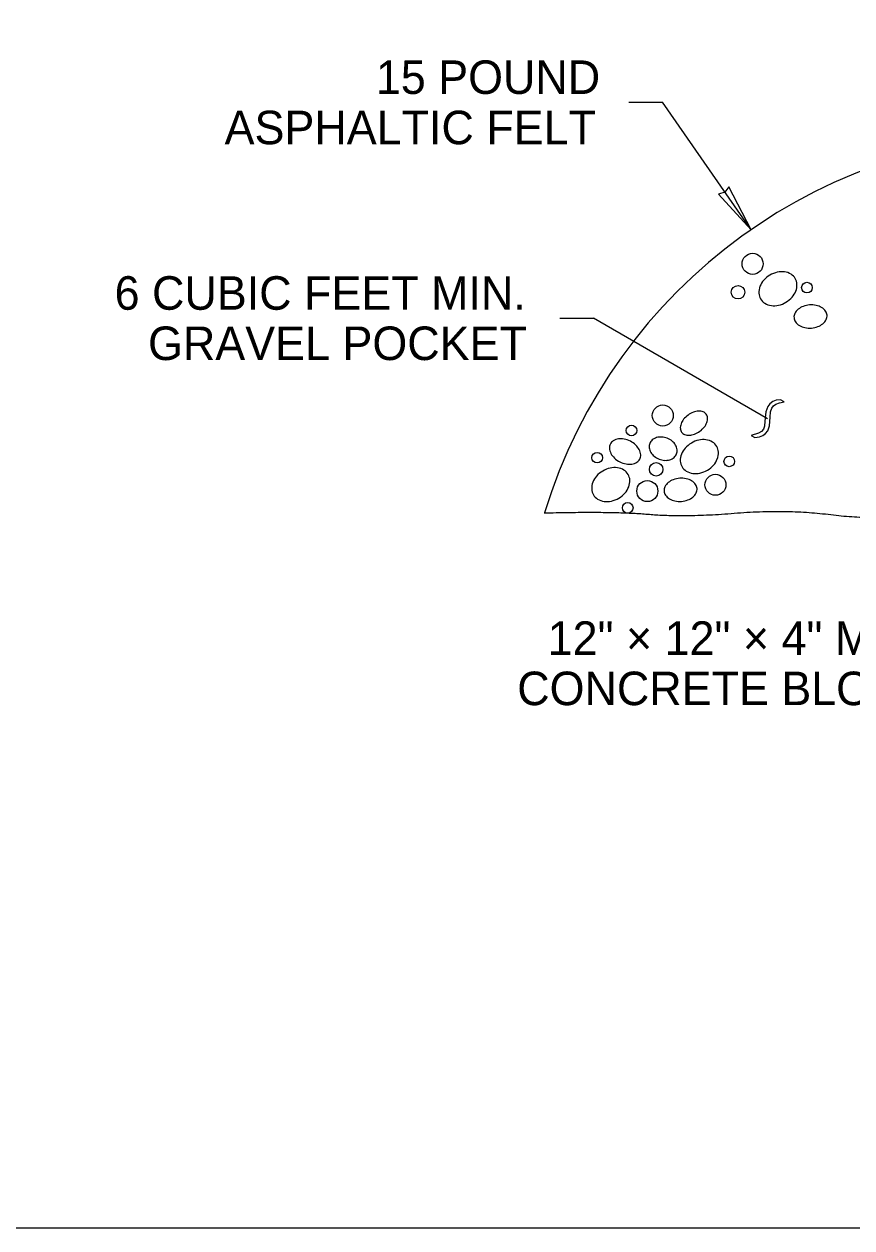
# Model space of a CAD drawing. Extents: x 99862 to 103151, y 100000 to 102076.
# Drawn here: x 101292 to 101687, y 100000 to 100574 of the extents above; entities that cross this region are included whole.
import ezdxf

# ---------------------------------------------------------------- set-up
doc = ezdxf.new("R2010")
doc.units = 0
for name, color, linetype in [('Level 1', 7, 'Continuous'), ('Level 10', 7, 'Continuous'), ('Level 15', 7, 'Continuous'), ('Level 20', 7, 'Continuous')]:
    doc.layers.add(name, color=color, linetype=linetype)

msp = doc.modelspace()

# ---------------------------------------------------------------- linework, layer by layer
at = {"layer": 'Level 1'}
msp.add_lwpolyline([(99862, 99999.5), (103151, 99999.5), (103151, 102075.5), (99862, 102075.5)], close=True, dxfattribs=at)
msp.add_arc((101784.76, 100265.79), 255.78, 89.02946, 162.96913, dxfattribs=at)
msp.add_open_spline([(101540.14, 100340.7), (101572.89, 100341.52), (101607.18, 100338.57), (101654.79, 100342.57), (101698.15, 100337.27), (101736.73, 100341.25), (101771.26, 100339.65)], degree=2, dxfattribs=at)
at = {"layer": 'Level 10'}
for centre, radius in [((101639.54, 100459.54), 5.02), ((101632.56, 100445.99), 3.22), ((101665.45, 100448.18), 2.54), ((101596.68, 100387.18), 5.02), ((101581.73, 100380.01), 2.54), ((101565.39, 100367.05), 2.54), ((101593.5, 100361.47), 3.22), ((101628.38, 100365.26), 2.54), ((101621.8, 100354.1), 5.02), ((101589.31, 100351.11), 5.02), ((101579.94, 100343.13), 2.54)]:
    msp.add_circle(centre, radius, dxfattribs=at)
for centre, radius, start, end in [((101653.97, 100443.66), 12.2, 102.54735, 120.55568), ((101653.45, 100446.01), 9.8, 82.43038, 102.54735), ((101653.69, 100447.84), 7.95, 58.38014, 82.43038), ((101654.73, 100449.53), 5.97, 30.55568, 58.38014), ((101650.45, 100445.93), 7.95, 158.68099, 182.73122), ((101652.17, 100445.25), 9.8, 138.56401, 158.68099), ((101653.97, 100443.66), 12.2, 120.55568, 138.56401), ((101654.73, 100449.53), 5.97, 2.73122, 30.55568), ((101652.75, 100449.43), 7.95, 338.68099, 2.73122), ((101648.47, 100445.83), 5.97, 182.73122, 210.55568), ((101649.23, 100451.7), 12.2, 300.55568, 318.56401), ((101651.03, 100450.1), 9.8, 318.56401, 338.68099), ((101648.47, 100445.83), 5.97, 210.55568, 238.38014), ((101649.51, 100447.52), 7.95, 238.38014, 262.43038), ((101649.75, 100449.35), 9.8, 262.43038, 282.54735), ((101649.23, 100451.7), 12.2, 282.54735, 300.55568), ((101665.17, 100433.14), 6.14, 129.27062, 153.66865), ((101666.55, 100431.45), 8.32, 110.47593, 129.27062), ((101667.58, 100428.69), 11.27, 94.34319, 110.47593), ((101667.58, 100428.69), 11.27, 78.21045, 94.34319), ((101668.19, 100431.57), 8.32, 59.41576, 78.21045), ((101669.3, 100433.45), 6.14, 35.01773, 59.41576), ((101663.18, 100434.12), 3.92, 153.66865, 184.34319), ((101663.18, 100434.12), 3.92, 184.34319, 215.01773), ((101665, 100435.4), 6.14, 215.01773, 239.41576), ((101669.13, 100435.71), 6.14, 309.27062, 333.66865), ((101671.12, 100434.73), 3.92, 4.34319, 35.01773), ((101671.12, 100434.73), 3.92, 333.66865, 4.34319), ((101666.11, 100437.28), 8.32, 239.41576, 258.21045), ((101666.71, 100440.16), 11.27, 258.21045, 274.34319), ((101666.71, 100440.16), 11.27, 274.34319, 290.47593), ((101667.74, 100437.4), 8.32, 290.47593, 309.27062), ((101615.21, 100378.46), 11.02, 126.08477, 141.32523), ((101615.21, 100378.46), 11.02, 110.84431, 126.08477), ((101614.08, 100381.43), 7.84, 92.74951, 110.84431), ((101613.96, 100383.75), 5.51, 68.28483, 92.74951), ((101614.81, 100385.89), 3.22, 36.08477, 68.28483), ((101614.81, 100385.89), 3.22, 3.88471, 36.08477), ((101612.52, 100385.73), 5.51, 339.42002, 3.88471), ((101610.55, 100381.26), 5.51, 159.42002, 183.88471), ((101608.26, 100381.11), 3.22, 183.88471, 216.08477), ((101612.72, 100380.45), 7.84, 141.32523, 159.42002), ((101607.86, 100388.54), 11.02, 306.08477, 321.32523), ((101610.35, 100386.55), 7.84, 321.32523, 339.42002), ((101575.15, 100371.79), 3.92, 122.21424, 152.88878), ((101576.33, 100369.91), 6.14, 97.81622, 122.21424), ((101576.63, 100367.74), 8.32, 79.02153, 97.81622), ((101576.07, 100364.85), 11.27, 62.88878, 79.02153), ((101576.07, 100364.85), 11.27, 46.75604, 62.88878), ((101594.42, 100372.3), 4.21, 130.69622, 158.66336), ((101595.36, 100371.21), 5.65, 106.62121, 130.69623), ((101595.75, 100369.92), 6.99, 86.57049, 106.62121), ((101595.64, 100368.16), 8.75, 68.66336, 86.57049), ((101595.64, 100368.16), 8.75, 50.75623, 68.66336), ((101596.75, 100369.52), 6.99, 30.70551, 50.75623), ((101608.26, 100381.11), 3.22, 216.08477, 248.28483), ((101609.11, 100383.24), 5.51, 248.28483, 272.74951), ((101616.5, 100363.53), 12.2, 120.55568, 138.56401), ((101608.99, 100385.56), 7.84, 272.74951, 290.84431), ((101616.5, 100363.53), 12.2, 102.54735, 120.55568), ((101607.86, 100388.54), 11.02, 290.84431, 306.08477), ((101615.97, 100365.88), 9.8, 82.43038, 102.54735), ((101616.22, 100367.71), 7.95, 58.38014, 82.43038), ((101617.26, 100369.4), 5.97, 30.55568, 58.38014), ((101575.15, 100371.79), 3.92, 152.88878, 183.56333), ((101577.36, 100371.93), 6.14, 183.56333, 207.96135), ((101579.29, 100372.95), 8.32, 207.96135, 226.75604), ((101578.08, 100367), 8.32, 27.96135, 46.75604), ((101580.01, 100368.02), 6.14, 3.56333, 27.96135), ((101582.23, 100368.16), 3.92, 332.88878, 3.56333), ((101594.42, 100372.3), 4.21, 158.66336, 186.63049), ((101595.86, 100372.46), 5.65, 186.63049, 210.70551), ((101597.01, 100373.15), 6.99, 210.70551, 230.75623), ((101599.34, 100370.38), 4.21, 310.69623, 338.66336), ((101597.91, 100370.21), 5.65, 6.63049, 30.70551), ((101599.34, 100370.38), 4.21, 338.66336, 6.63049), ((101612.97, 100365.8), 7.95, 158.68099, 182.73122), ((101614.69, 100365.13), 9.8, 138.56401, 158.68099), ((101617.26, 100369.4), 5.97, 2.73122, 30.55568), ((101615.28, 100369.3), 7.95, 338.68099, 2.73122), ((101581.31, 100375.1), 11.27, 226.75604, 242.88878), ((101581.31, 100375.1), 11.27, 242.88878, 259.02152), ((101580.75, 100372.2), 8.32, 259.02152, 277.81622), ((101581.05, 100370.04), 6.14, 277.81622, 302.21424), ((101582.23, 100368.16), 3.92, 302.21424, 332.88878), ((101598.12, 100374.51), 8.75, 230.75623, 248.66336), ((101598.12, 100374.51), 8.75, 248.66336, 266.57049), ((101598.02, 100372.76), 6.99, 266.57049, 286.62121), ((101598.4, 100371.47), 5.65, 286.62121, 310.69623), ((101611, 100365.7), 5.97, 182.73122, 210.55568), ((101611, 100365.7), 5.97, 210.55568, 238.38014), ((101611.76, 100371.57), 12.2, 300.55568, 318.56401), ((101613.56, 100369.98), 9.8, 318.56401, 338.68099), ((101572.44, 100351.77), 9.8, 138.56401, 158.68099), ((101574.24, 100350.18), 12.2, 120.55568, 138.56401), ((101574.24, 100350.18), 12.2, 102.54735, 120.55568), ((101573.72, 100352.53), 9.8, 82.43038, 102.54735), ((101573.96, 100354.36), 7.95, 58.38014, 82.43038), ((101575, 100356.04), 5.97, 30.55568, 58.38014), ((101575, 100356.04), 5.97, 2.73122, 30.55568), ((101605.59, 100345.97), 11.27, 94.34319, 110.47593), ((101605.59, 100345.97), 11.27, 78.21045, 94.34319), ((101612.03, 100367.39), 7.95, 238.38014, 262.43038), ((101606.19, 100348.85), 8.32, 59.41576, 78.21045), ((101612.28, 100369.22), 9.8, 262.43038, 282.54735), ((101611.76, 100371.57), 12.2, 282.54735, 300.55568), ((101570.72, 100352.44), 7.95, 158.68099, 182.73122), ((101568.74, 100352.35), 5.97, 182.73122, 210.55568), ((101571.3, 100356.62), 9.8, 318.56401, 338.68099), ((101573.02, 100355.95), 7.95, 338.68099, 2.73122), ((101601.19, 100351.4), 3.92, 153.66865, 184.34319), ((101601.19, 100351.4), 3.92, 184.34319, 215.01773), ((101603.18, 100350.42), 6.14, 129.27062, 153.66865), ((101604.56, 100348.73), 8.32, 110.47593, 129.27062), ((101607.31, 100350.73), 6.14, 35.01773, 59.41576), ((101609.12, 100352.01), 3.92, 4.34319, 35.01773), ((101609.12, 100352.01), 3.92, 333.66865, 4.34319), ((101568.74, 100352.35), 5.97, 210.55568, 238.38014), ((101569.78, 100354.03), 7.95, 238.38014, 262.43038), ((101570.02, 100355.86), 9.8, 262.43038, 282.54735), ((101569.5, 100358.21), 12.2, 282.54735, 300.55568), ((101569.5, 100358.21), 12.2, 300.55568, 318.56401), ((101603.01, 100352.68), 6.14, 215.01773, 239.41576), ((101604.12, 100354.56), 8.32, 239.41576, 258.21045), ((101604.72, 100357.44), 11.27, 258.21045, 274.34319), ((101604.72, 100357.44), 11.27, 274.34319, 290.47593), ((101605.75, 100354.68), 8.32, 290.47593, 309.27062), ((101607.13, 100352.99), 6.14, 309.27062, 333.66865)]:
    msp.add_arc(centre, radius, start, end, dxfattribs=at)
at = {"layer": 'Level 15'}
for p, q in [((101580.49, 100536.61), (101596.49, 100536.61)), ((101638.76, 100475.81), (101596.49, 100536.61)), ((101547.6, 100433.63), (101563.6, 100433.63)), ((101646.7, 100385.65), (101563.6, 100433.63))]:
    msp.add_line(p, q, dxfattribs=at)
msp.add_lwpolyline([(101638.76, 100475.81), (101628.18, 100496.26), (101626.34, 100493.69), (101623.28, 100492.85)], close=True, dxfattribs=at)
at = {"layer": 'Level 20'}
for p, q in [((101646.73, 100391.41), (101645.8, 100388.86)), ((101647.8, 100392.81), (101646.73, 100391.41)), ((101649.17, 100393.83), (101647.8, 100392.81)), ((101648.74, 100390.67), (101649.56, 100391.72)), ((101650.84, 100394.46), (101649.17, 100393.83)), ((101649.56, 100391.72), (101650.66, 100392.52)), ((101650.66, 100392.52), (101652.28, 100393.14)), ((101652.82, 100394.72), (101650.84, 100394.46)), ((101652.28, 100393.14), (101654.65, 100393.66)), ((101654.65, 100393.66), (101652.82, 100394.72)), ((101645.8, 100388.86), (101645.42, 100384.46)), ((101647.61, 100382.23), (101647.88, 100386.31)), ((101647.88, 100386.31), (101648.1, 100388.85)), ((101648.1, 100388.85), (101648.74, 100390.67)), ((101644.69, 100380.64), (101643.77, 100379.56)), ((101645.22, 100382.04), (101644.69, 100380.64)), ((101645.42, 100384.46), (101645.22, 100382.04)), ((101645.72, 100378.61), (101646.72, 100379.93)), ((101646.72, 100379.93), (101647.61, 100382.23)), ((101642.37, 100378.68), (101638.81, 100377.7)), ((101638.81, 100377.7), (101640.64, 100376.64)), ((101640.64, 100376.64), (101642.76, 100377.01)), ((101643.77, 100379.56), (101642.37, 100378.68)), ((101642.76, 100377.01), (101644.42, 100377.65)), ((101644.42, 100377.65), (101645.72, 100378.61))]:
    msp.add_line(p, q, dxfattribs=at)

# ---------------------------------------------------------------- texts
for s, p in [('15 POUND', (101459.81, 100540.61)), ('ASPHALTIC FELT', (101387.66, 100516.61)), ('6 CUBIC FEET MIN.', (101335.2, 100437.63)), ('GRAVEL POCKET', (101351.13, 100413.63)), ('12" × 12" × 4" MIN.', (101541.78, 100272.95)), ('CONCRETE BLOCK', (101527.24, 100248.95))]:
    msp.add_text(s, height=16, dxfattribs=at).set_placement(p)

doc.saveas('drawing.dxf')
